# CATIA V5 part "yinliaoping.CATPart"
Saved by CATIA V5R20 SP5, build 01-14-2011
Part number: 饮料瓶
Bounding box of the stored display mesh (mm): x -25 to 25, y -25 to 25, z 0 to 120
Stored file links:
  E:\yinliaoping.CATPart
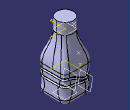
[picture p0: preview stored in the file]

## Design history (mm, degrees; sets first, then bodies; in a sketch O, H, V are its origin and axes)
Set1
  Sketch1 on xy-plane, origin (0, 0, 0), H (1, 0, 0), V (0, 1, 0)
    line L1 (25, 25) -> (25, -25)
    line L2 (25, -25) -> (-25, -25)
    line L3 (-25, -25) -> (-25, 25)
    line L4 (-25, 25) -> (25, 25)
    length L1 = 50
    length L4 = 50
    vertical: L1 V, L3 V
    horizontal: L2 H, L4 H
    equidistance: L1 L3 O, L2 L4 O
  Sketch2 on face of Pad1 from Sketch1.L4, origin (0, 25, 0), H (-1, 0, 0), V (0, 0, 1)
    spline S1 through (-30, 40) (-10, 40) (10, 30) (30, 40)
  Extrude1: Lim1 56, Lim2 14, Element1 Sketch2
  MultiSel1: CommonCtxFeats ({extract ExtractElem face of Pad1 from Sketch1.L4}; {extract ExtractElem face of Fillet1}; {extract ExtractElem face of Pad1 from Sketch1.L3}; {extract ExtractElem face of Fillet1}; {extract ExtractElem face of Pad1 from Sketch1.L1}; {extract ExtractElem face of Fillet1}; {extract ExtractElem face of Pad1 from Sketch1.L2}; {extract ExtractElem face of Fillet1})
  Join1: Elements ({intersect ToIntersect1 {extract ExtractElem face of Pad1 from Sketch1.L4}, ToIntersect2 Extrude2}; {intersect ToIntersect1 {extract ExtractElem face of Fillet1}, ToIntersect2 Extrude2}; {intersect ToIntersect1 {extract ExtractElem face of Fillet1}, ToIntersect2 Extrude2}; {intersect ToIntersect1 {extract ExtractElem face of Pad1 from Sketch1.L1}, ToIntersect2 Extrude2}; {intersect ToIntersect1 {extract ExtractElem face of Fillet1}, ToIntersect2 Extrude2}; {intersect ToIntersect1 {extract ExtractElem face of Pad1 from Sketch1.L2}, ToIntersect2 Extrude2}; {intersect ToIntersect1 {extract ExtractElem face of Fillet1}, ToIntersect2 Extrude2}; {intersect ToIntersect1 {extract ExtractElem face of Pad1 from Sketch1.L3}, ToIntersect2 Extrude2})
  Join2: Elements ({intersect ToIntersect1 {extract ExtractElem face of Pad1 from Sketch1.L4}, ToIntersect2 Extrude1}; {intersect ToIntersect1 {extract ExtractElem face of Fillet1}, ToIntersect2 Extrude1}; {intersect ToIntersect1 {extract ExtractElem face of Pad1 from Sketch1.L3}, ToIntersect2 Extrude1}; {intersect ToIntersect1 {extract ExtractElem face of Fillet1}, ToIntersect2 Extrude1}; {intersect ToIntersect1 {extract ExtractElem face of Pad1 from Sketch1.L1}, ToIntersect2 Extrude1}; {intersect ToIntersect1 {extract ExtractElem face of Fillet1}, ToIntersect2 Extrude1}; {intersect ToIntersect1 {extract ExtractElem face of Pad1 from Sketch1.L2}, ToIntersect2 Extrude1}; {intersect ToIntersect1 {extract ExtractElem face of Fillet1}, ToIntersect2 Extrude1})
  Plane1: type Normal, Curve Join2, RefPoint vertex [face of MultiSel1 | face of MultiSel1]
  Circle1: type CtrRad, Start 0, End 180, Radius 2, Center vertex [face of MultiSel1 | face of MultiSel1], Support Plane1, FirstDirection (0, 1, 0)
Body1 (main body)
  Pad1: profile Sketch1, direction (0, 0, 1), length 50
  Fillet1: on edge [face of Pad1 from Sketch1.L4 | face of Pad1 from Sketch1.L1]; edge [face of Pad1 from Sketch1.L3 | face of Pad1 from Sketch1.L4]; edge [face of Pad1 from Sketch1.L1 | face of Pad1 from Sketch1.L2]; edge [face of Pad1 from Sketch1.L2 | face of Pad1 from Sketch1.L3]
  Fillet2: radius 8, on start face of Pad1
  Plane2: type Offset, RefPlane xy-plane, Offset 100
  Sketch3 on Plane2, origin (0, 0, 100), H (1, 0, 0), V (0, 1, 0)
    circle A1 centre (0, 0) radius 15
    radius A1 = 15
  Pad2: profile Sketch3, direction (0, 0, 1), length 20
  Point1: type OnSurface, Support face of Pad2 from Sketch3.A1, Length 28.488, Direction (-0.757, -0.5775, -0.3057)
  Sketch4 on face of Pad1 from Sketch1.L4, origin (0, 25, 0), H (-1, 0, 0), V (0, 0, 1)
    spline S1 through (-70, 20) (-20, 30) (40, 20) (90, 30)
  Sketch5 on start face of Pad2, origin (0, 0, 100), H (1, 0, 0), V (0, -1, 0)
    reference projected circle E1 centre (0, 0) radius 15 from edge [start face of Pad2 | face of Pad2 from Sketch3.A1]
    radius E1 = 15 (reference)
  Sketch6 on end face of Pad1, origin (0, 0, 50), H (1, 0, 0), V (0, 1, 0)
    point P1 (-25, 0)
    distance P1 V = 25
    coincidence: P1 H
  Loft1: solid, Sections ({boundary Boundary {extract ExtractElem end face of Pad1}}; {boundary Boundary {extract ExtractElem start face of Pad2}}), StartFace end face of Pad1, EndFace start face of Pad2
  Extrude2: Lim1 54, Lim2 14, Element1 Sketch4
  MultiSel2: CommonCtxFeats ({extract ExtractElem face of Pad1 from Sketch1.L4}; {extract ExtractElem face of Fillet1}; {extract ExtractElem face of Fillet1}; {extract ExtractElem face of Pad1 from Sketch1.L1}; {extract ExtractElem face of Fillet1}; {extract ExtractElem face of Pad1 from Sketch1.L2}; {extract ExtractElem face of Fillet1}; {extract ExtractElem face of Pad1 from Sketch1.L3})
  Slot1: profile Circle1, centre curve Join2
  Plane3: type Normal, Curve Join1, RefPoint vertex [face of MultiSel2 | face of MultiSel2]
  Circle2: type CtrRad, Start 0, End 180, Radius 2, Center vertex [face of MultiSel2 | face of MultiSel2], Support Plane3, FirstDirection (0, 1, 0)
  Slot2: profile Circle2, centre curve Join1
